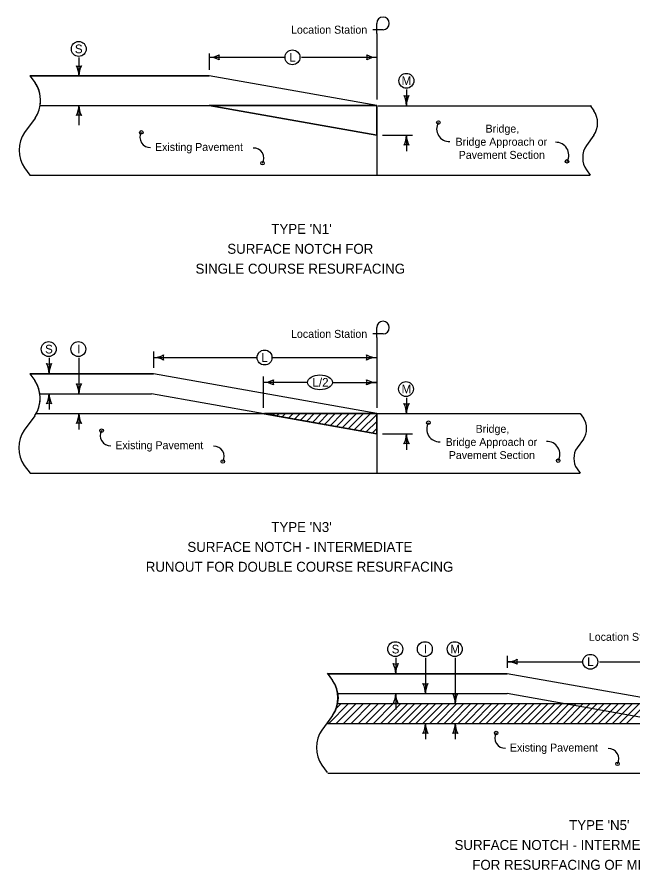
# Model space of a CAD drawing. Extents: x 10133 to 81668, y 2218 to 11018.
# Drawn here: x 14718 to 15959, y 2218 to 3935 of the extents above; entities that cross this region are included whole.
import ezdxf

# ---------------------------------------------------------------- set-up
doc = ezdxf.new("R2010")
doc.units = 0
for name, color, linetype in [('Default', 7, 'Continuous'), ('dsnNonPlotable', 7, 'Continuous'), ('dsnShtPlotShapeBatchPrint', 7, 'Continuous'), ('dsnStdBlock', 7, 'Continuous'), ('dsnstdblockInterim', 7, 'Continuous'), ('dsnStdBlockNotModified', 7, 'Continuous'), ('dsnStgShadingPropPav', 7, 'Continuous'), ('Level 2', 7, 'Continuous'), ('Level 7', 7, 'Continuous')]:
    doc.layers.add(name, color=color, linetype=linetype)

msp = doc.modelspace()

# ---------------------------------------------------------------- linework, layer by layer
at = {"layer": 'Default'}
for p, q in [((15442.9, 3757), (15105.4, 3757)), ((15105.4, 3757), (15442.9, 3697)), ((15442.9, 3697), (15442.9, 3757))]:
    msp.add_line(p, q, dxfattribs=at)
msp.add_lwpolyline([(15216.3, 3136.4), (15442.9, 3096.1), (15442.9, 3136.7), (15216.7, 3136.7), (15216.3, 3136.4)], dxfattribs=at)
at = {"layer": 'dsnNonPlotable'}
for p, q in [((15705.4, 2613.2), (15344.3, 2613.2)), ((15344.3, 2613.2), (15354.1, 2599.8)), ((16042.9, 2553.2), (15705.4, 2613.2)), ((15354.1, 2529.1), (15342.4, 2513.2)), ((15342.4, 2513.2), (16042.9, 2513.2))]:
    msp.add_line(p, q, dxfattribs=at)
msp.add_arc((15305.8, 2564.5), 59.8, 323.7718, 36.2282, dxfattribs=at)
at = {"layer": 'dsnStdBlock'}
for p, q in [((15442.9, 3902), (15442.9, 3922.3)), ((15455.6, 3909.6), (15435.3, 3909.6)), ((15442.9, 3902), (15442.9, 3769)), ((14842.9, 3853.4), (14842.9, 3817)), ((15105.4, 3862), (15105.4, 3829)), ((15105.4, 3854), (15256.7, 3854)), ((15291.7, 3854), (15442.9, 3854)), ((14744.3, 3817), (15105.4, 3817)), ((14744.3, 3817), (14755, 3802.4)), ((15442.9, 3757), (15105.4, 3817)), ((15502.9, 3789.2), (15502.9, 3757.2)), ((14765, 3757), (15105.4, 3757)), ((14842.9, 3757), (14842.9, 3717.5)), ((15442.9, 3697), (15105.4, 3757)), ((15105.4, 3757), (15442.9, 3757)), ((15442.9, 3757), (15442.9, 3697)), ((15445.7, 3756.2), (15875.7, 3756.2)), ((15872.9, 3756.7), (15880.4, 3746.5)), ((14755, 3731.7), (14733.5, 3702.4)), ((15442.9, 3697), (15442.9, 3617)), ((15454.9, 3697), (15514.9, 3697)), ((15502.9, 3697), (15502.9, 3665)), ((15880.4, 3697.1), (15865.4, 3676.6)), ((14733.5, 3631.7), (14744.3, 3617)), ((15865.4, 3627.2), (15872.9, 3617)), ((14744.3, 3617), (15872.9, 3617)), ((15455.6, 3297.3), (15435.3, 3297.3)), ((15442.9, 3289.7), (15442.9, 3310)), ((15442.9, 3289.7), (15442.9, 3148.7)), ((14782.9, 3249.1), (14782.9, 3217.1)), ((14842.9, 3249.1), (14842.9, 3176.7)), ((14992.9, 3261.7), (14992.9, 3228.7)), ((14992.9, 3249.7), (15201.9, 3249.7)), ((15231.9, 3249.7), (15442.9, 3249.7)), ((14744.3, 3216.7), (14992.9, 3216.7)), ((14744.3, 3216.7), (14754.1, 3203.3)), ((15442.9, 3136.7), (14992.9, 3216.7)), ((15214.4, 3211.7), (15214.4, 3148.7)), ((15303.6, 3199.7), (15214.4, 3199.7)), ((15353.6, 3199.7), (15442.9, 3199.7)), ((14764.2, 3176.7), (14989.4, 3176.7)), ((14782.9, 3177.1), (14782.9, 3145.1)), ((15442.9, 3096.1), (14989.4, 3176.7)), ((15502.9, 3168.7), (15502.9, 3136.7)), ((14754.1, 3132.6), (14732.6, 3103.3)), ((14756.7, 3136.7), (15442.9, 3136.7)), ((14842.9, 3137.1), (14842.9, 3105.1)), ((15214.4, 3136.7), (15214.4, 3136.7)), ((15214.4, 3136.7), (15442.9, 3136.7)), ((15215.1, 3136.6), (15215.3, 3136.7)), ((15216.3, 3136.4), (15216.7, 3136.7)), ((15229.5, 3134), (15232.2, 3136.7)), ((15234.3, 3133.2), (15237.8, 3136.7)), ((15241.5, 3131.9), (15246.3, 3136.7)), ((15252.3, 3130), (15259, 3136.7)), ((15265.5, 3127.6), (15274.6, 3136.7)), ((15277.5, 3125.5), (15288.7, 3136.7)), ((15289.5, 3123.4), (15302.9, 3136.7)), ((15301.5, 3121.2), (15317, 3136.7)), ((15313.5, 3119.1), (15331.2, 3136.7)), ((15325.5, 3117), (15345.3, 3136.7)), ((15337.5, 3114.8), (15359.4, 3136.7)), ((15349.5, 3112.7), (15373.6, 3136.7)), ((15361.6, 3110.5), (15387.7, 3136.7)), ((15373.6, 3108.4), (15401.9, 3136.7)), ((15385.6, 3106.3), (15416, 3136.7)), ((15397.6, 3104.1), (15430.1, 3136.7)), ((15409.6, 3102), (15442.9, 3135.3)), ((15442.9, 3136.7), (15852.9, 3136.7)), ((15442.9, 3136.7), (15442.9, 3096.1)), ((15852.9, 3136.7), (15859.3, 3127.9)), ((15421.6, 3099.9), (15442.9, 3121.2)), ((15433.6, 3097.7), (15442.9, 3107)), ((15442.9, 3096.1), (15442.9, 3016.7)), ((15454.9, 3096.1), (15514.9, 3096.1)), ((15502.9, 3096.1), (15502.9, 3064.1)), ((15859.3, 3085.5), (15846.5, 3067.9)), ((14732.6, 3032.6), (14744.6, 3016.7)), ((15846.5, 3025.5), (15852.9, 3016.7)), ((14744.6, 3016.7), (15852.9, 3016.7)), ((15481.1, 2645.2), (15481.1, 2613.2)), ((15541.1, 2645.2), (15541.1, 2573.2)), ((15601.1, 2645.2), (15601.1, 2553.2)), ((15705.4, 2649.2), (15705.4, 2625.2)), ((15705.4, 2637.2), (15856.7, 2637.2)), ((15891.7, 2637.2), (16042.9, 2637.2)), ((15343.3, 2614.5), (15354.1, 2599.8)), ((15344.3, 2613.2), (15705.4, 2613.2)), ((16042.9, 2553.2), (15705.4, 2613.2)), ((15364.2, 2573.2), (15705.4, 2573.2)), ((15481.1, 2573.2), (15481.1, 2541.2)), ((15601.2, 2571.4), (15603, 2573.2)), ((16042.9, 2513.2), (15705.4, 2573.2)), ((15346.3, 2513.2), (15386.2, 2553.2)), ((15361.3, 2513.2), (15401.2, 2553.2)), ((15361.4, 2543.3), (15371.2, 2553.2)), ((15363.9, 2553.2), (15817.9, 2553.2)), ((15376.3, 2513.2), (15416.2, 2553.2)), ((15391.3, 2513.2), (15431.2, 2553.2)), ((15406.3, 2513.2), (15446.2, 2553.2)), ((15421.3, 2513.2), (15461.2, 2553.2)), ((15436.3, 2513.2), (15476.2, 2553.2)), ((15451.3, 2513.2), (15491.2, 2553.2)), ((15465.4, 2513.2), (15505.4, 2553.2)), ((15479.5, 2513.2), (15519.5, 2553.2)), ((15493.7, 2513.2), (15533.7, 2553.2)), ((15507.8, 2513.2), (15547.8, 2553.2)), ((15522, 2513.2), (15562, 2553.2)), ((15536.1, 2513.2), (15576.1, 2553.2)), ((15550.2, 2513.2), (15590.2, 2553.2)), ((15564.4, 2513.2), (15604.4, 2553.2)), ((15578.5, 2513.2), (15618.5, 2553.2)), ((15592.7, 2513.2), (15632.7, 2553.2)), ((15606.8, 2513.2), (15646.8, 2553.2)), ((15621, 2513.2), (15661, 2553.2)), ((15635.1, 2513.2), (15675.1, 2553.2)), ((15649.2, 2513.2), (15689.2, 2553.2)), ((15663.4, 2513.2), (15703.4, 2553.2)), ((15677.5, 2513.2), (15717.5, 2553.2)), ((15691.7, 2513.2), (15731.7, 2553.2)), ((15705.8, 2513.2), (15745.8, 2553.2)), ((15720, 2513.2), (15760, 2553.2)), ((15734.1, 2513.2), (15774.1, 2553.2)), ((15748.2, 2513.2), (15788.2, 2553.2)), ((15762.4, 2513.2), (15802.4, 2553.2)), ((15776.5, 2513.2), (15816.5, 2553.2)), ((15790.7, 2513.2), (15830.7, 2553.2)), ((15804.8, 2513.2), (15844.8, 2553.2)), ((15817.9, 2553.2), (16042.9, 2553.2)), ((15818.9, 2513.2), (15858.9, 2553.2)), ((15833.1, 2513.2), (15873.1, 2553.2)), ((15847.2, 2513.2), (15887.2, 2553.2)), ((15861.4, 2513.2), (15901.4, 2553.2)), ((15875.5, 2513.2), (15915.5, 2553.2)), ((15889.7, 2513.2), (15929.7, 2553.2)), ((15903.8, 2513.2), (15943.8, 2553.2)), ((15917.9, 2513.2), (15957.9, 2553.2)), ((15932.1, 2513.2), (15972.1, 2553.2)), ((15946.2, 2513.2), (15986.2, 2553.2)), ((15354.1, 2529.1), (15332.6, 2499.8)), ((15342.4, 2513.2), (16042.9, 2513.2)), ((15541.1, 2513.2), (15541.1, 2481.2)), ((15601.1, 2513.2), (15601.1, 2481.2)), ((15332.6, 2429.1), (15343.3, 2414.5)), ((15344.3, 2413.2), (16441.4, 2413.2))]:
    msp.add_line(p, q, dxfattribs=at)
msp.add_lwpolyline([(15214.4, 3136.7), (15442.9, 3136.7), (15442.9, 3096.1)], close=True, dxfattribs=at)
for centre, radius in [((14842.7, 3870.9), 15), ((15273.2, 3854), 15), ((15502.7, 3806.7), 15), ((14968.6, 3702.9), 3.56), ((15212.9, 3640.8), 3.56), ((14782.1, 3266.6), 15), ((14841.7, 3266.6), 15), ((15216.9, 3249.7), 15), ((15501.9, 3186.2), 15), ((15547.1, 3118.4), 3.56), ((14888.6, 3102.6), 3.56), ((15132.9, 3040.5), 3.56), ((15808.4, 3042.2), 3.56), ((15480.2, 2662.7), 15), ((15539.9, 2662.7), 15), ((15600.1, 2662.7), 15), ((15873.2, 2637.2), 15), ((15683.6, 2493.9), 3.56), ((15928, 2431.9), 3.56)]:
    msp.add_circle(centre, radius, dxfattribs=at)
for centre, radius, start, end in [((15455.6, 3922.3), 12.7, 270, 180), ((15589.2, 3710), 25.6, 150.0683, 272.8436), ((14986.3, 3692.7), 20.4, 150.0683, 272.8436), ((15804.3, 3657.3), 25.6, 330.0683, 92.8436), ((15195.2, 3651), 20.4, 330.0683, 92.8436), ((15455.6, 3310), 12.7, 270, 180), ((14992.9, 3292.9), 43.2, 270, 298.0725), ((14992.9, 3206.5), 43.2, 61.9275, 90), ((15029.1, 3249.7), 16.7, 162.2666, 197.7334), ((15406.7, 3249.7), 16.7, 342.2666, 17.7333), ((15442.9, 3292.9), 43.2, 241.9275, 270), ((15442.9, 3206.5), 43.2, 90, 118.0725), ((14782.9, 3253.3), 16.7, 252.2666, 287.7333), ((14739.7, 3217.1), 43.2, 360, 28.0725), ((14826.1, 3217.1), 43.2, 151.9275, 180), ((14842.9, 3212.9), 16.7, 252.2666, 287.7333), ((14799.7, 3176.7), 43.2, 360, 28.0725), ((14886.1, 3176.7), 43.2, 151.9275, 180), ((15214.4, 3242.9), 43.2, 270, 298.0725), ((15214.4, 3156.5), 43.2, 61.9275, 90), ((15250.6, 3199.7), 16.7, 162.2666, 197.7334), ((15406.7, 3199.7), 16.7, 342.2666, 17.7333), ((15442.9, 3242.9), 43.2, 241.9275, 270), ((15442.9, 3156.5), 43.2, 90, 118.0725), ((14739.7, 3177.1), 43.2, 331.9275, 360), ((14826.1, 3177.1), 43.2, 180, 208.0725), ((14782.9, 3140.9), 16.7, 72.2666, 107.7334), ((15502.9, 3172.9), 16.7, 252.2666, 287.7333), ((15459.7, 3136.7), 43.2, 360, 28.0725), ((15546.1, 3136.7), 43.2, 151.9275, 180), ((14799.7, 3137.1), 43.2, 331.9275, 360), ((14886.1, 3137.1), 43.2, 180, 208.0725), ((14842.9, 3100.9), 16.7, 72.2666, 107.7334), ((15569.2, 3105.7), 25.6, 150.0683, 272.8436), ((14906.3, 3092.4), 20.4, 150.0683, 272.8436), ((15459.7, 3096.1), 43.2, 331.9275, 360), ((15546.1, 3096.1), 43.2, 180, 208.0725), ((15502.9, 3059.9), 16.7, 72.2666, 107.7334), ((15786.3, 3055), 25.6, 330.0683, 92.8436), ((15115.2, 3050.7), 20.4, 330.0683, 92.8436), ((15481.1, 2649.4), 16.7, 252.2666, 287.7333), ((15437.9, 2613.2), 43.2, 360, 28.0725), ((15524.2, 2613.2), 43.2, 151.9275, 180), ((15705.4, 2680.4), 43.2, 270, 298.0725), ((15705.4, 2594), 43.2, 61.9275, 90), ((15741.6, 2637.2), 16.7, 162.2666, 197.7334), ((15541.1, 2609.4), 16.7, 252.2666, 287.7333), ((15497.9, 2573.2), 43.2, 360, 28.0725), ((15584.2, 2573.2), 43.2, 151.9275, 180), ((15437.9, 2573.2), 43.2, 331.9275, 360), ((15524.2, 2573.2), 43.2, 180, 208.0725), ((15601.1, 2589.4), 16.7, 252.2666, 287.7333), ((15557.9, 2553.2), 43.2, 360, 28.0725), ((15644.2, 2553.2), 43.2, 151.9275, 180), ((15481.1, 2537), 16.7, 72.2666, 107.7334), ((15497.9, 2513.2), 43.2, 331.9275, 360), ((15584.2, 2513.2), 43.2, 180, 208.0725), ((15557.9, 2513.2), 43.2, 331.9275, 360), ((15644.2, 2513.2), 43.2, 180, 208.0725), ((15541.1, 2477), 16.7, 72.2666, 107.7334), ((15601.1, 2477), 16.7, 72.2666, 107.7334), ((15701.3, 2483.7), 20.4, 150.0683, 272.8436), ((15910.2, 2442.1), 20.4, 330.0683, 92.8436)]:
    msp.add_arc(centre, radius, start, end, dxfattribs=at)
for centre, major_axis in [((14729.1, 3767), (0, -50)), ((15862.3, 3721.8), (0, -34.9)), ((14759.4, 3667), (0, 50)), ((15883.5, 3651.9), (0, 34.9)), ((14728.2, 3168), (0, -50)), ((15843.8, 3106.7), (0, -30)), ((14758.5, 3068), (0, 50)), ((15862, 3046.7), (0, 30)), ((15328.2, 2564.5), (0, -50)), ((15358.5, 2464.5), (0, 50))]:
    msp.add_ellipse(centre, major_axis=major_axis, ratio=0.732645, start_param=0.785398, end_param=2.356194, dxfattribs=at)
msp.add_ellipse((15328.6, 3199.7), major_axis=(25, 0), ratio=0.6, dxfattribs=at)
at = {"layer": 'dsnstdblockInterim'}
for p, q in [((14744.3, 3817), (14755, 3802.4)), ((15442.9, 3757), (15105.4, 3817)), ((15105.4, 3757), (15442.9, 3697)), ((15442.9, 3697), (15442.9, 3757)), ((14992.9, 3216.7), (14744.3, 3216.7)), ((14744.3, 3216.7), (14754.1, 3203.3)), ((15442.9, 3136.7), (14992.9, 3216.7)), ((14756.7, 3136.7), (15442.9, 3136.7))]:
    msp.add_line(p, q, dxfattribs=at)
for points in [[(15105.4, 3817), (14842.9, 3817), (14744.3, 3817)], [(14765, 3757), (14842.9, 3757), (15105.4, 3757)]]:
    msp.add_lwpolyline(points, dxfattribs=at)
for centre, start_param in [((14729.1, 3767), 1.369431), ((14728.2, 3168), 0.895403)]:
    msp.add_ellipse(centre, major_axis=(0, -50), ratio=0.732645, start_param=start_param, end_param=2.356194, dxfattribs=at)
at = {"layer": 'dsnStgShadingPropPav'}
for centre, radius, start, end in [((15105.4, 3896.5), 42.5, 270, 298.0725), ((15105.4, 3811.5), 42.5, 61.9275, 90), ((15141, 3854), 16.4, 162.2666, 197.7334), ((15407.3, 3854), 16.4, 342.2666, 17.7334), ((15442.9, 3896.5), 42.5, 241.9275, 270), ((15442.9, 3811.5), 42.5, 90, 118.0725), ((14842.9, 3852.7), 16.4, 252.2666, 287.7333), ((14800.4, 3817), 42.5, 360, 28.0725), ((14885.4, 3817), 42.5, 151.9275, 180), ((15502.9, 3792.9), 16.4, 252.2666, 287.7333), ((15460.4, 3757.2), 42.5, 360, 28.0725), ((15545.4, 3757.2), 42.5, 151.9275, 180), ((14800.4, 3757), 42.5, 331.9275, 360), ((14885.4, 3757), 42.5, 180, 208.0725), ((14842.9, 3721.4), 16.4, 72.2666, 107.7334), ((15460.4, 3697), 42.5, 331.9275, 360), ((15545.4, 3697), 42.5, 180, 208.0725), ((15502.9, 3661.4), 16.4, 72.2666, 107.7334)]:
    msp.add_arc(centre, radius, start, end, dxfattribs=at)
at = {"layer": 'Level 7'}
for centre in [(15567.1, 3722.7), (15826.4, 3644.5)]:
    msp.add_circle(centre, 3.54, dxfattribs=at)

# ---------------------------------------------------------------- texts
at = {"layer": 'dsnShtPlotShapeBatchPrint'}
for s, height, p in [('S', 17.5, (14774.8, 3257.9)), ('I', 17.5, (14839.6, 3257.9)), ('L', 17.5, (15210.6, 3241)), ('L/2', 17.5, (15313.4, 3191)), ('M', 17.5, (15493, 3177.5)), ('Bridge,', 16, (15642.2, 3098.1)), ('Bridge Approach or', 16, (15581.8, 3071.7)), ('Pavement Section', 16, (15588.1, 3045.3))]:
    msp.add_text(s, height=height, dxfattribs=at).set_placement(p)
at = {"layer": 'dsnStdBlockNotModified'}
for s, height, p in [('Location Station', 16, (15270.3, 3901.6)), ('S', 17.5, (14834.8, 3862.2)), ('L', 17.5, (15266.9, 3845.3)), ('M', 17.5, (15493, 3798)), ('Bridge,', 16, (15662.2, 3702.4)), ('Bridge Approach or', 16, (15601.8, 3676)), ('Existing Pavement', 16, (14996.3, 3665.5)), ('Pavement Section', 16, (15608.1, 3649.6)), ("TYPE 'N1'", 20, (15230.6, 3498.5)), ('SURFACE NOTCH FOR', 20, (15141.9, 3458.5)), ('SINGLE COURSE RESURFACING', 20, (15077.9, 3418.5)), ('Location Station', 16, (15270.3, 3289.3)), ('Existing Pavement', 16, (14916.3, 3065.2)), ('Location Station', 16, (15870.3, 2679.4)), ('S', 17.5, (15473, 2654)), ('I', 17.5, (15537.7, 2654)), ('M', 17.5, (15591.1, 2654)), ('L', 17.5, (15866.9, 2628.5)), ('Existing Pavement', 16, (15711.3, 2456.5)), ("TYPE 'N5'", 20, (15830.6, 2298.5)), ('SURFACE NOTCH - INTERMEDIATE RUNOUT', 20, (15599.8, 2258.5)), ('FOR RESURFACING OF MILLED AREAS', 20, (15635.5, 2218.5))]:
    msp.add_text(s, height=height, dxfattribs=at).set_placement(p)
at = {"layer": 'Level 2'}
for s, p in [("TYPE 'N3'", (15230.6, 2898.5)), ('SURFACE NOTCH - INTERMEDIATE', (15061.5, 2858.5)), ('RUNOUT FOR DOUBLE COURSE RESURFACING', (14977.6, 2818.5))]:
    msp.add_text(s, height=20, dxfattribs=at).set_placement(p)

doc.saveas('drawing.dxf')
